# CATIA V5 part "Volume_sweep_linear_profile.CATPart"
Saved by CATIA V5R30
Part number: Part1
Bounding box of the stored display mesh (mm): x -63.725 to 63.725, y -58.359 to 47.359, z -20 to 20
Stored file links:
  D:\PROJECTS\CATIA V56R 2020\Resources\Parts File\c17_catia_v6_6r2020_prt\Volume_sweep_linear_profile.CATPart
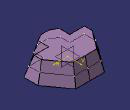
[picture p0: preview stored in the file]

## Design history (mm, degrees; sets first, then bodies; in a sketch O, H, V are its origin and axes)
Set1
  Sketch1 on xy-plane, origin (0, 0, 0), H (1, 0, 0), V (0, 1, 0)
    point P1 (0, 42)
    line L1 (0, 42) -> (-27.5, 42)
    point P2 (-27.5, 42)
    line L2 (-27.5, 42) -> (-58.3665, 0)
    point P3 (-58.3665, 0)
    line L3 (-58.3665, 0) -> (-58.3665, -23)
    point P4 (-58.3665, -23)
    line L4 (-58.3665, -23) -> (-27.5, -23)
    point P5 (-27.5, -23)
    line L5 (-27.5, -23) -> (-27.5, -42.8964)
    point P6 (-27.5, -42.8964)
    line L6 (-27.5, -42.8964) -> (-10, -53)
    point P7 (-10, -53)
    line L7 (-10, -53) -> (0, -53)
    point P8 (0, -53)
    reference intersected line E1 through (0, 0) direction (0, 1) from yz-plane
    point P11 (0, 0)
    construction line L8 through (0, 0) direction (0, 1)
    point P12 (0, 42)
    point P13 (27.5, 42)
    point P14 (58.3665, 0)
    point P15 (58.3665, -23)
    point P16 (27.5, -23)
    point P17 (27.5, -42.8964)
    point P18 (10, -53)
    point P19 (0, -53)
    line L9 (0, 42) -> (27.5, 42)
    line L10 (27.5, 42) -> (58.3665, 0)
    line L11 (58.3665, 0) -> (58.3665, -23)
    line L12 (58.3665, -23) -> (27.5, -23)
    line L13 (27.5, -23) -> (27.5, -42.8964)
    line L14 (27.5, -42.8964) -> (10, -53)
    line L15 (10, -53) -> (0, -53)
    distance P14 P13 V = 42
    distance P13 P2 = 55
    distance P15 P14 = 23
    distance L11 L8 = 58.3665
    angle L14 L15 = 30
    distance P18 P7 = 20
    distance P17 P6 = 55
    distance L9 L15 = 95
    coincidence: P1 V, P3 H, P8 V, P7 L15, P8 L15, P18 L7, P19 L7
    horizontal: L1 H, L4 H, L7 H, L15 H
    vertical: L3 V, L5 V
    symmetry: O P11 E1, V L8 E1, P1 P12 E1, P2 P13 E1, P3 P14 E1, P4 P15 E1, P5 P16 E1, P6 P17 E1, P7 P18 E1, P8 P19 E1, L1 L9 E1, L2 L10 E1, L3 L11 E1, L4 L12 E1, L5 L13 E1, L6 L14 E1, L7 L15 E1
  Sweep1: type Segment, GuideCrv Sketch1, Length1 20, Length2 20, Angle 15, DraftDirection xy-plane
Body1 (main body)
